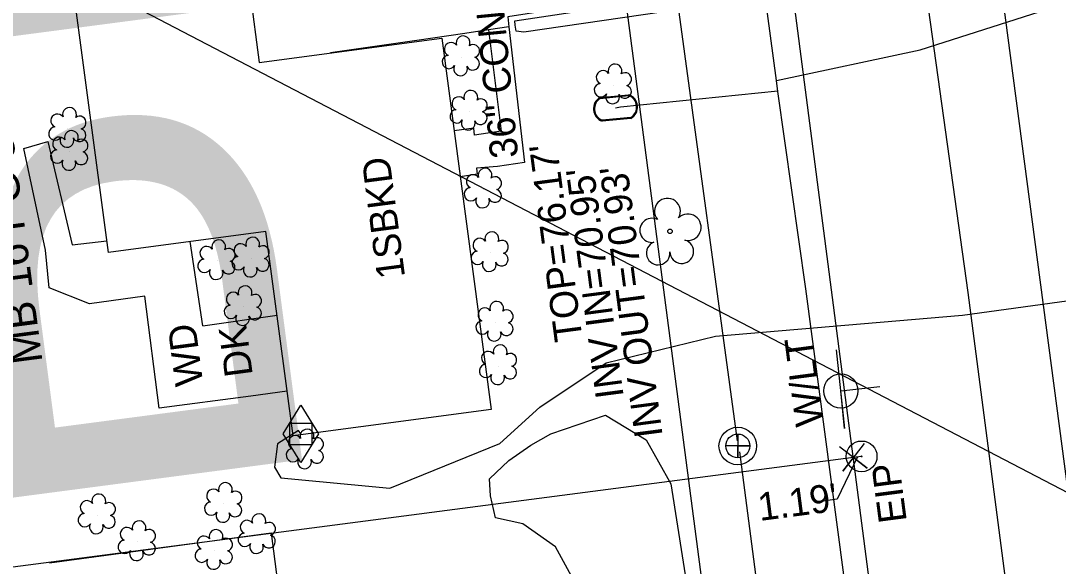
# Model space of a CAD drawing. Extents: x 2364404 to 2371833, y 798876 to 809754.
# Drawn here: x 2368462.5 to 2368611.1, y 806170.3 to 806248.5 of the extents above; entities that cross this region are included whole.
import ezdxf

# ---------------------------------------------------------------- set-up
doc = ezdxf.new("R2010")
doc.units = 0
for name, color, linetype in [('Exist Building', 7, 'Continuous'), ('Exist Building Text', 7, 'Continuous'), ('Exist Horizontal Alignment Direction Label', 7, 'Continuous'), ('Exist Horizontal Baseline Alignment Station Label', 7, 'Continuous'), ('Exist Other Culture Area Outline', 7, 'Continuous'), ('Exist Other Culture Area Outline Text', 7, 'Continuous'), ('Exist Other Culture Fence Line', 7, 'Continuous'), ('Exist Property Corner CELL', 7, 'Continuous'), ('Exist Property Deed Book Text', 7, 'Continuous'), ('Exist Property Iron Pin CELL', 7, 'Continuous'), ('Exist Property Iron Pin Text', 7, 'Continuous'), ('Exist Property Line', 7, 'Continuous'), ('Exist Property Line Leader', 7, 'Continuous'), ('Exist Property Line Text', 7, 'Continuous'), ('Exist Right of Way Easement Line', 7, 'Continuous'), ('Exist Right of Way Line', 7, 'Continuous'), ('Exist Roads EOP', 7, 'Continuous'), ('Exist Roads EOP Other', 7, 'Continuous'), ('Exist Utilities Gas Meter CELL', 7, 'Continuous'), ('Exist Utilities Gas UG Line SUE LOS B', 7, 'Continuous'), ('Exist Utilities Power Joint Use Telephone CELL', 7, 'Continuous'), ('Exist Utilities Power Joint Use Telephone Text', 7, 'Continuous'), ('Exist Utilities Sanitary Sewer Manhole CELL', 7, 'Continuous'), ('Exist Utilities Sanitary Sewer Manhole Top Elevation', 7, 'Continuous'), ('Exist Utilities Sanitary Sewer UG Line', 7, 'Continuous'), ('Exist Utilities Sanitary Sewer UG Line Invert Elevation', 7, 'Continuous'), ('Exist Utilities Water Meter CELL', 7, 'Continuous'), ('Exist Utilities Water UG Line SUE LOS B', 7, 'Continuous'), ('Exist Vegetation Hedge Row', 7, 'Continuous'), ('Exist Vegetation Shrub CELL', 7, 'Continuous'), ('Exist Vegetation Tree CELL', 7, 'Continuous'), ('Exist Vegetation Woods Line', 7, 'Continuous'), ('Prop Horizontal Alignment', 7, 'Continuous')]:
    doc.layers.add(name, color=color, linetype=linetype)

msp = doc.modelspace()

# ---------------------------------------------------------------- linework, layer by layer
at = {"layer": 'Exist Building'}
msp.add_lwpolyline([(2368522.77, 806246.02), (2368529.84, 806192.79), (2368501.49, 806189.02), (2368497.6, 806218.31), (2368475.04, 806215.31), (2368469.24, 806258.99), (2368494.03, 806262.28), (2368496.65, 806242.55)], close=True, dxfattribs=at)
at = {"layer": 'Exist Horizontal Alignment Direction Label'}
msp.add_lwpolyline([(2368418.28, 805963.81), (2368402.28, 806290.43), (2368679.85, 806145.74)], dxfattribs=at)
at = {"layer": 'Exist Other Culture Area Outline'}
for q in [(2368486.74, 806216.87), (2368499.2, 806206.32)]:
    msp.add_line((2368488.56, 806204.79), q, dxfattribs=at)
for points in [[(2368529.48, 806247.21), (2368531.28, 806232.69), (2368527.47, 806232.14), (2368527.39, 806233.1), (2368524.54, 806232.72)], [(2368532.37, 806247.64), (2368534.64, 806228.18), (2368530.78, 806227.65), (2368527.78, 806227.38), (2368527.85, 806226.52), (2368525.41, 806226.15)], [(2368500.64, 806195.45), (2368495.45, 806194.72), (2368482.31, 806192.99), (2368480.23, 806209.05), (2368472.31, 806207.93), (2368466.57, 806210.22), (2368466, 806215.66), (2368462.9, 806230.23), (2368466.34, 806231.23), (2368469.84, 806216.39), (2368474.82, 806216.96)]]:
    msp.add_lwpolyline(points, dxfattribs=at)
at = {"layer": 'Exist Other Culture Fence Line'}
for q in [(2368466.6, 806170.8), (2368499.91, 806162.86)]:
    msp.add_line((2368498.37, 806175.09), q, dxfattribs=at)
at = {"layer": 'Exist Property Corner CELL'}
msp.add_line((2368581.74, 806185.93), (2368581.74, 806185.93), dxfattribs=at)
msp.add_lwpolyline([(2368583.27, 806187.92), (2368580.22, 806183.95), (2368581.74, 806185.93), (2368583.72, 806184.41), (2368579.76, 806187.46)], dxfattribs=at)
at = {"layer": 'Exist Property Iron Pin CELL'}
for radius in [2.2, 0.0707]:
    msp.add_circle((2368582.92, 806186.09), radius, dxfattribs=at)
at = {"layer": 'Exist Property Line'}
for p, q in [((2368582.92, 806186.09), (2368581.74, 806185.93)), ((2368581.74, 806185.93), (2368417.33, 806164.46))]:
    msp.add_line(p, q, dxfattribs=at)
at = {"layer": 'Exist Property Line Leader'}
msp.add_lwpolyline([(2368582.33, 806186.01), (2368579.41, 806179.95), (2368577.04, 806179.61)], dxfattribs=at)
at = {"layer": 'Exist Right of Way Easement Line'}
msp.add_line((2368631.3, 805622.61), (2368519.57, 806478.09), dxfattribs=at)
at = {"layer": 'Exist Right of Way Line'}
msp.add_line((2368614.63, 805933.13), (2368545.92, 806461.27), dxfattribs=at)
at = {"layer": 'Exist Roads EOP'}
msp.add_lwpolyline([(2368584.76, 806311.27), (2368588.82, 806280.28), (2368585.76, 806276.49), (2368588.03, 806255.81), (2368592.19, 806252.14), (2368598.11, 806209.59), (2368604.6, 806160.15), (2368609.05, 806125.26), (2368607.46, 806122.2), (2368608.86, 806108.67), (2368611.24, 806106.9), (2368613.5, 806091.72)], dxfattribs=at)
at = {"layer": 'Exist Roads EOP Other'}
for points in [[(2368588.03, 806255.81), (2368582.24, 806256.42), (2368573.5, 806255.38), (2368552.23, 806252.23), (2368532.25, 806249.06), (2368532.37, 806247.64), (2368529.48, 806247.21)], [(2368529.48, 806247.21), (2368526.08, 806246.71), (2368519.23, 806245.67), (2368506.84, 806243.9)]]:
    msp.add_lwpolyline(points, dxfattribs=at)
at = {"layer": 'Exist Utilities Gas Meter CELL'}
msp.add_line((2368502.61, 806189.31), (2368502.61, 806189.31), dxfattribs=at)
for points in [[(2368500.07, 806189.31), (2368502.61, 806193.43), (2368505.14, 806189.31), (2368502.61, 806185.2), (2368500.07, 806189.31)], [(2368501.03, 806190.85), (2368504.18, 806190.85), (2368504.18, 806187.74), (2368501.03, 806187.74), (2368501.03, 806190.85)]]:
    msp.add_lwpolyline(points, dxfattribs=at)
at = {"layer": 'Exist Utilities Gas UG Line SUE LOS B'}
msp.add_lwpolyline([(2368502.61, 806189.31), (2368502.24, 806189.8), (2368499.23, 806187.9), (2368498.84, 806184.53), (2368499.71, 806183.02), (2368515.36, 806181.52), (2368531.11, 806187.94), (2368536.84, 806193.16), (2368546.34, 806199.49), (2368562.01, 806203.31), (2368597.35, 806206.34), (2368621.32, 806209.61), (2368621.61, 806209.68)], dxfattribs=at)
at = {"layer": 'Exist Utilities Power Joint Use Telephone CELL'}
msp.add_line((2368579.93, 806195.47), (2368579.93, 806195.47), dxfattribs=at)
msp.add_lwpolyline([(2368579.29, 806201.37), (2368580.49, 806190.09), (2368579.92, 806195.46), (2368585.53, 806196.08)], dxfattribs=at)
msp.add_circle((2368579.94, 806195.46), 2.45, dxfattribs=at)
at = {"layer": 'Exist Utilities Sanitary Sewer Manhole CELL'}
msp.add_lwpolyline([(2368565.18, 806189.29), (2368565.18, 806185.87), (2368565.18, 806187.58), (2368566.89, 806187.58), (2368563.47, 806187.58)], dxfattribs=at)
for radius in [2.69, 1.71]:
    msp.add_circle((2368565.18, 806187.58), radius, dxfattribs=at)
at = {"layer": 'Exist Utilities Sanitary Sewer UG Line'}
for p, q in [((2368521.45, 806509.43), (2368565.1, 806188.32)), ((2368565.44, 806186.73), (2368604.1, 805891.33))]:
    msp.add_line(p, q, dxfattribs=at)
at = {"layer": 'Exist Utilities Water Meter CELL'}
msp.add_line((2368547.67, 806236.03), (2368547.67, 806236.03), dxfattribs=at)
for points in [[(2368545.48, 806237.53), (2368549.54, 806237.92)], [(2368545.49, 806237.39), (2368549.55, 806237.78)], [(2368549.85, 806234.67), (2368545.77, 806234.28)], [(2368549.86, 806234.53), (2368545.78, 806234.14)]]:
    msp.add_lwpolyline(points, dxfattribs=at)
for centre, radius, start, end in [((2368546.37, 806235.9), 1.86, 118.7002, 251.5015), ((2368546.38, 806235.9), 1.73, 120.8231, 249.3045), ((2368548.96, 806236.15), 1.86, 299.1705, 71.8305), ((2368548.97, 806236.16), 1.73, 300.6493, 70.395)]:
    msp.add_arc(centre, radius, start, end, dxfattribs=at)
at = {"layer": 'Exist Utilities Water UG Line SUE LOS B'}
for points in [[(2368591.16, 806087.23), (2368586.61, 806120.34), (2368584.18, 806145.32), (2368581.3, 806162.29), (2368574.92, 806210.1), (2368570.92, 806238.38), (2368570.73, 806239.93), (2368558.61, 806330.34), (2368551.92, 806375.78), (2368545.8, 806416.25), (2368536.4, 806481.89), (2368535.55, 806488.9), (2368535.57, 806489.47), (2368535.43, 806489.89), (2368531.58, 806524.39), (2368524.43, 806581.98), (2368519.2, 806620.08), (2368510.97, 806683.25)], [(2368570.73, 806239.93), (2368591.31, 806244.34), (2368614.18, 806251.68), (2368631.91, 806256.26), (2368632.69, 806256.34)], [(2368547.67, 806236.03), (2368548.37, 806236.18), (2368570.93, 806238.47)]]:
    msp.add_lwpolyline(points, dxfattribs=at)
at = {"layer": 'Exist Vegetation Hedge Row'}
msp.add_lwpolyline([(2368574.29, 806252.72), (2368534.56, 806246.9), (2368533.44, 806247.02), (2368533.29, 806247.88), (2368533.24, 806248.48), (2368574.28, 806254.71), (2368574.29, 806252.72)], dxfattribs=at)
at = {"layer": 'Exist Vegetation Shrub CELL'}
for p, q in [((2368525.61, 806243.31), (2368525.61, 806243.31)), ((2368547.37, 806239.28), (2368547.37, 806239.28)), ((2368526.71, 806235.51), (2368526.71, 806235.51)), ((2368469.23, 806233.05), (2368469.23, 806233.05)), ((2368469.51, 806229.75), (2368469.51, 806229.75)), ((2368528.75, 806224.36), (2368528.75, 806224.36)), ((2368495.48, 806214.48), (2368495.48, 806214.48)), ((2368529.72, 806215.24), (2368529.72, 806215.24)), ((2368490.59, 806214.09), (2368490.59, 806214.09)), ((2368494.38, 806207.51), (2368494.38, 806207.51)), ((2368530.42, 806205.27), (2368530.42, 806205.27)), ((2368530.92, 806199.04), (2368530.92, 806199.04)), ((2368503.26, 806186.97), (2368503.26, 806186.97)), ((2368491.56, 806179.3), (2368491.56, 806179.3)), ((2368473.44, 806177.66), (2368473.44, 806177.66)), ((2368496.36, 806174.83), (2368496.36, 806174.83)), ((2368479.18, 806173.82), (2368479.18, 806173.82)), ((2368490.21, 806172.57), (2368490.21, 806172.57))]:
    msp.add_line(p, q, dxfattribs=at)
for centre, radius, start, end in [((2368525.84, 806245.35), 0.99, 334.8391, 200.4717), ((2368524.12, 806244.43), 0.968, 35.8908, 245.4216), ((2368527.28, 806244.17), 0.929, 284.4567, 126.0861), ((2368523.81, 806242.6), 0.955, 95.1099, 327.9534), ((2368527.24, 806242.38), 0.937, 204.9913, 73.4601), ((2368525.48, 806241.62), 0.984, 151.2797, 21.387), ((2368545.88, 806240.4), 0.968, 35.8908, 245.4216), ((2368547.6, 806241.32), 0.99, 334.8391, 200.4717), ((2368549.04, 806240.14), 0.929, 284.4567, 126.0861), ((2368545.57, 806238.57), 0.955, 95.1099, 327.9534), ((2368526.94, 806237.55), 0.99, 334.8391, 200.4717), ((2368547.24, 806237.59), 0.984, 151.2797, 21.387), ((2368549, 806238.35), 0.937, 204.9913, 73.4601), ((2368525.22, 806236.64), 0.968, 35.8908, 245.4216), ((2368528.38, 806236.38), 0.929, 284.4567, 126.0861), ((2368467.75, 806234.18), 0.968, 35.8908, 245.4216), ((2368469.46, 806235.09), 0.99, 334.8391, 200.4717), ((2368524.91, 806234.81), 0.955, 95.1099, 327.9534), ((2368528.34, 806234.58), 0.937, 204.9913, 73.4601), ((2368470.9, 806233.92), 0.929, 284.4567, 126.0861), ((2368526.58, 806233.83), 0.984, 151.2797, 21.387), ((2368467.43, 806232.34), 0.955, 95.1099, 327.9534), ((2368469.74, 806231.79), 0.99, 334.8391, 200.4717), ((2368470.87, 806232.12), 0.937, 204.9913, 73.4601), ((2368468.02, 806230.88), 0.968, 35.8908, 245.4216), ((2368469.1, 806231.37), 0.984, 151.2797, 21.387), ((2368471.18, 806230.62), 0.929, 284.4567, 126.0861), ((2368467.71, 806229.05), 0.955, 95.1099, 327.9534), ((2368471.14, 806228.82), 0.937, 204.9913, 73.4601), ((2368469.38, 806228.07), 0.984, 151.2797, 21.387), ((2368527.27, 806225.49), 0.968, 35.8908, 245.4216), ((2368528.98, 806226.4), 0.99, 334.8391, 200.4717), ((2368530.42, 806225.23), 0.929, 284.4567, 126.0861), ((2368526.95, 806223.66), 0.955, 95.1099, 327.9534), ((2368530.39, 806223.43), 0.937, 204.9913, 73.4601), ((2368528.62, 806222.68), 0.984, 151.2797, 21.387), ((2368495.7, 806216.52), 0.99, 334.8391, 200.4717), ((2368528.23, 806216.37), 0.968, 35.8908, 245.4216), ((2368529.95, 806217.28), 0.99, 334.8391, 200.4717), ((2368489.11, 806215.22), 0.968, 35.8908, 245.4216), ((2368490.82, 806216.13), 0.99, 334.8391, 200.4717), ((2368492.27, 806214.96), 0.929, 284.4567, 126.0861), ((2368493.99, 806215.6), 0.968, 35.8908, 245.4216), ((2368497.15, 806215.34), 0.929, 284.4567, 126.0861), ((2368531.39, 806216.11), 0.929, 284.4567, 126.0861), ((2368488.79, 806213.39), 0.955, 95.1099, 327.9534), ((2368493.67, 806213.77), 0.955, 95.1099, 327.9534), ((2368497.11, 806213.55), 0.937, 204.9913, 73.4601), ((2368527.92, 806214.54), 0.955, 95.1099, 327.9534), ((2368531.35, 806214.31), 0.937, 204.9913, 73.4601), ((2368490.47, 806212.41), 0.984, 151.2797, 21.387), ((2368492.23, 806213.16), 0.937, 204.9913, 73.4601), ((2368495.35, 806212.79), 0.984, 151.2797, 21.387), ((2368529.59, 806213.56), 0.984, 151.2797, 21.387), ((2368494.61, 806209.55), 0.99, 334.8391, 200.4717), ((2368492.9, 806208.64), 0.968, 35.8908, 245.4216), ((2368496.05, 806208.38), 0.929, 284.4567, 126.0861), ((2368492.58, 806206.81), 0.955, 95.1099, 327.9534), ((2368496.02, 806206.59), 0.937, 204.9913, 73.4601), ((2368528.94, 806206.4), 0.968, 35.8908, 245.4216), ((2368530.65, 806207.31), 0.99, 334.8391, 200.4717), ((2368532.09, 806206.14), 0.929, 284.4567, 126.0861), ((2368494.25, 806205.83), 0.984, 151.2797, 21.387), ((2368528.62, 806204.57), 0.955, 95.1099, 327.9534), ((2368530.29, 806203.59), 0.984, 151.2797, 21.387), ((2368532.06, 806204.34), 0.937, 204.9913, 73.4601), ((2368529.44, 806200.17), 0.968, 35.8908, 245.4216), ((2368531.15, 806201.08), 0.99, 334.8391, 200.4717), ((2368532.59, 806199.91), 0.929, 284.4567, 126.0861), ((2368529.12, 806198.34), 0.955, 95.1099, 327.9534), ((2368532.56, 806198.11), 0.937, 204.9913, 73.4601), ((2368530.79, 806197.36), 0.984, 151.2797, 21.387), ((2368501.78, 806188.1), 0.968, 35.8908, 245.4216), ((2368503.49, 806189.01), 0.99, 334.8391, 200.4717), ((2368504.93, 806187.84), 0.929, 284.4567, 126.0861), ((2368501.46, 806186.27), 0.955, 95.1099, 327.9534), ((2368504.9, 806186.04), 0.937, 204.9913, 73.4601), ((2368503.13, 806185.29), 0.984, 151.2797, 21.387), ((2368491.79, 806181.34), 0.99, 334.8391, 200.4717), ((2368473.67, 806179.7), 0.99, 334.8391, 200.4717), ((2368490.08, 806180.43), 0.968, 35.8908, 245.4216), ((2368493.24, 806180.17), 0.929, 284.4567, 126.0861), ((2368471.96, 806178.78), 0.968, 35.8908, 245.4216), ((2368475.11, 806178.53), 0.929, 284.4567, 126.0861), ((2368489.76, 806178.6), 0.955, 95.1099, 327.9534), ((2368493.2, 806178.37), 0.937, 204.9913, 73.4601), ((2368471.64, 806176.95), 0.955, 95.1099, 327.9534), ((2368475.08, 806176.73), 0.937, 204.9913, 73.4601), ((2368491.43, 806177.62), 0.984, 151.2797, 21.387), ((2368496.59, 806176.87), 0.99, 334.8391, 200.4717), ((2368473.31, 806175.97), 0.984, 151.2797, 21.387), ((2368477.7, 806174.95), 0.968, 35.8908, 245.4216), ((2368479.41, 806175.86), 0.99, 334.8391, 200.4717), ((2368480.85, 806174.69), 0.929, 284.4567, 126.0861), ((2368494.88, 806175.96), 0.968, 35.8908, 245.4216), ((2368498.04, 806175.7), 0.929, 284.4567, 126.0861), ((2368488.73, 806173.7), 0.968, 35.8908, 245.4216), ((2368490.44, 806174.61), 0.99, 334.8391, 200.4717), ((2368491.88, 806173.44), 0.929, 284.4567, 126.0861), ((2368494.56, 806174.13), 0.955, 95.1099, 327.9534), ((2368498, 806173.9), 0.937, 204.9913, 73.4601), ((2368477.38, 806173.11), 0.955, 95.1099, 327.9534), ((2368480.82, 806172.89), 0.937, 204.9913, 73.4601), ((2368488.41, 806171.86), 0.955, 95.1099, 327.9534), ((2368496.24, 806173.15), 0.984, 151.2797, 21.387), ((2368479.05, 806172.13), 0.984, 151.2797, 21.387), ((2368490.08, 806170.89), 0.984, 151.2797, 21.387), ((2368491.85, 806171.64), 0.937, 204.9913, 73.4601)]:
    msp.add_arc(centre, radius, start, end, dxfattribs=at)
at = {"layer": 'Exist Vegetation Tree CELL'}
msp.add_line((2368555.48, 806218.34), (2368555.48, 806218.34), dxfattribs=at)
msp.add_circle((2368555.48, 806218.34), 0.326, dxfattribs=at)
for centre, radius, start, end in [((2368555.1, 806221.21), 1.86, 330.1651, 219.7134), ((2368552.88, 806218.49), 1.73, 62.6636, 279.3457), ((2368558.03, 806218.92), 1.9, 257.1011, 134.1999), ((2368553.78, 806215.22), 1.69, 111.5671, 6.231), ((2368557.16, 806215.44), 1.7, 181.2822, 74.56)]:
    msp.add_arc(centre, radius, start, end, dxfattribs=at)
at = {"layer": 'Exist Vegetation Woods Line'}
msp.add_lwpolyline([(2368546.25, 806191.99), (2368552.04, 806188.47), (2368555.57, 806182.15), (2368562.38, 806139.08), (2368560.84, 806134.42), (2368557.52, 806131.72), (2368553.09, 806135.79), (2368548.36, 806143.43), (2368541.38, 806168.91), (2368539.06, 806173.14), (2368534.41, 806176.44), (2368530.49, 806177.3), (2368529.74, 806180.45), (2368529.6, 806182.86), (2368532.39, 806185.48), (2368535.53, 806187.69), (2368538.41, 806189.33), (2368546.25, 806191.99)], dxfattribs=at)
at = {"layer": 'Prop Horizontal Alignment'}
msp.add_line((2368631.17, 806039.71), (2368556.15, 806607.59), dxfattribs=at)

# ---------------------------------------------------------------- texts
at = {"layer": 'Exist Building Text'}
msp.add_text('1SBKD', height=4, rotation=97.4798, dxfattribs=at).set_placement((2368517.54, 806211.82))
at = {"layer": 'Exist Horizontal Baseline Alignment Station Label'}
msp.add_text('BL-110', height=73.5, rotation=97.4798, dxfattribs=at).set_placement((2368503.81, 806177.62))
at = {"layer": 'Exist Other Culture Area Outline Text'}
for s, rotation, p in [('36" CONC', 95.5199, (2368533.75, 806229)), ('WD', 97.4798, (2368488.62, 806196.47)), ('DK', 97.4798, (2368495.72, 806197.75))]:
    msp.add_text(s, height=4, rotation=rotation, dxfattribs=at).set_placement(p)
at = {"layer": 'Exist Property Deed Book Text'}
msp.add_text('MB 16 PG 35', height=4.5, rotation=97.4798, dxfattribs=at).set_placement((2368465.61, 806199.63))
at = {"layer": 'Exist Property Iron Pin Text'}
msp.add_text('EIP', height=4, rotation=97.4798, dxfattribs=at).set_placement((2368589.4, 806176.81))
at = {"layer": 'Exist Property Line Text'}
msp.add_text("1.19'", height=4, rotation=7.441, dxfattribs=at).set_placement((2368568.33, 806176.83))
at = {"layer": 'Exist Utilities Power Joint Use Telephone Text'}
msp.add_text('W/LT', height=4, rotation=97.4798, dxfattribs=at).set_placement((2368577.48, 806190.68))
at = {"layer": 'Exist Utilities Sanitary Sewer Manhole Top Elevation'}
msp.add_text("TOP=76.17'", height=4, rotation=97.4798, dxfattribs=at).set_placement((2368542.96, 806202.81))
at = {"layer": 'Exist Utilities Sanitary Sewer UG Line Invert Elevation'}
for s, p in [("INV IN=70.95'", (2368548.85, 806194.65)), ("INV OUT=70.93'", (2368554.43, 806189.03))]:
    msp.add_text(s, height=4, rotation=97.4798, dxfattribs=at).set_placement(p)

doc.saveas('drawing.dxf')
